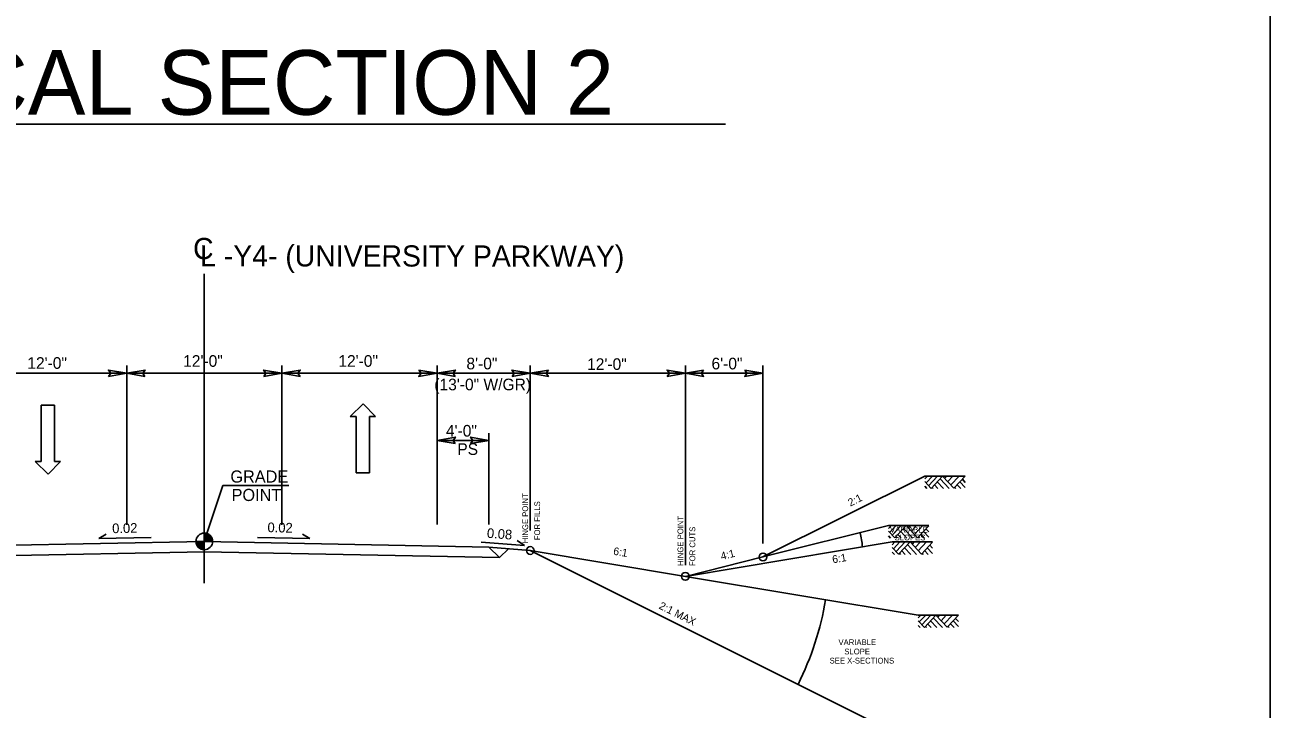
# Model space of a CAD drawing. Extents: x 1904401 to 1905163, y 193929 to 194736.
# Drawn here: x 1904562 to 1904658.3, y 194245.4 to 194298.3 of the extents above; entities that cross this region are included whole.
import ezdxf

# ---------------------------------------------------------------- set-up
doc = ezdxf.new("R2010")
doc.units = 0
for name, color, linetype in [('Old_Level_2', 7, 'Continuous'), ('Prop Lane Arrow CELL', 7, 'Continuous'), ('Typical Arrow Superelevation CELL', 7, 'Continuous'), ('Typical Grade Point Symbol CELL', 7, 'Continuous'), ('Typical Hinge Slope Arterial CELL', 7, 'Continuous'), ('Typical Terminator CELL', 7, 'Continuous'), ('Typical Text Centerline CELL', 7, 'Continuous'), ('Typical Text Grade Point CELL', 7, 'Continuous')]:
    doc.layers.add(name, color=color, linetype=linetype)

msp = doc.modelspace()

# ---------------------------------------------------------------- linework, layer by layer
at = {"layer": 'Old_Level_2'}
msp.add_lwpolyline([(1904502.509, 194232.165), (1904658.329, 194232.165), (1904658.329, 194351.235), (1904502.509, 194351.235)], close=True, dxfattribs=at)
at = {"layer": 'Prop Lane Arrow CELL'}
for p, q in [((1904534.927, 194290.618), (1904616.206, 194290.618)), ((1904569.917, 194271.945), (1904569.917, 194259.611)), ((1904581.917, 194271.945), (1904581.917, 194259.611)), ((1904593.917, 194271.945), (1904593.917, 194259.633)), ((1904601.117, 194271.945), (1904601.117, 194259.174)), ((1904613.115, 194271.945), (1904613.115, 194256.508)), ((1904619.114, 194271.945), (1904619.114, 194258.167)), ((1904569.917, 194271.345), (1904557.917, 194271.345)), ((1904581.917, 194271.345), (1904569.917, 194271.345)), ((1904581.917, 194271.345), (1904593.917, 194271.345)), ((1904619.114, 194271.345), (1904593.917, 194271.345)), ((1904563.311, 194268.879), (1904564.338, 194268.879)), ((1904563.311, 194264.521), (1904563.311, 194268.879)), ((1904564.338, 194268.879), (1904564.338, 194264.521)), ((1904588.197, 194268.973), (1904587.201, 194267.993)), ((1904589.162, 194267.993), (1904588.197, 194268.973)), ((1904587.201, 194267.993), (1904587.668, 194267.993)), ((1904587.668, 194267.993), (1904587.668, 194263.635)), ((1904588.695, 194263.635), (1904588.695, 194267.993)), ((1904588.695, 194267.993), (1904589.162, 194267.993)), ((1904597.917, 194266.721), (1904597.917, 194259.633)), ((1904597.917, 194266.153), (1904593.917, 194266.153)), ((1904563.84, 194263.541), (1904562.844, 194264.521)), ((1904562.844, 194264.521), (1904563.311, 194264.521)), ((1904564.805, 194264.521), (1904563.84, 194263.541)), ((1904564.338, 194264.521), (1904564.805, 194264.521)), ((1904587.668, 194263.635), (1904588.695, 194263.635)), ((1904631.838, 194263.392), (1904631.634, 194263.173)), ((1904632.119, 194262.436), (1904631.634, 194262.958)), ((1904632.222, 194263.392), (1904631.725, 194262.859)), ((1904632.622, 194263.392), (1904631.926, 194262.645)), ((1904633.008, 194263.391), (1904632.119, 194262.436)), ((1904633.07, 194262.426), (1904632.59, 194262.941)), ((1904633.514, 194262.426), (1904632.81, 194263.18)), ((1904633.886, 194262.448), (1904633.008, 194263.391)), ((1904633.325, 194263.392), (1904633.166, 194263.221)), ((1904633.807, 194263.392), (1904633.408, 194262.961)), ((1904634.285, 194263.392), (1904633.646, 194262.704)), ((1904634.754, 194263.383), (1904633.886, 194262.448)), ((1904634.754, 194262.502), (1904634.344, 194262.941)), ((1904634.754, 194262.901), (1904634.531, 194263.141)), ((1904631.795, 194262.426), (1904631.634, 194262.598)), ((1904632.276, 194262.426), (1904632.194, 194262.515)), ((1904632.63, 194262.426), (1904632.37, 194262.706)), ((1904634.036, 194262.426), (1904633.95, 194262.517)), ((1904634.409, 194262.426), (1904634.136, 194262.718)), ((1904629.018, 194259.557), (1904628.814, 194259.338)), ((1904629.299, 194258.601), (1904628.814, 194259.123)), ((1904629.402, 194259.557), (1904628.905, 194259.024)), ((1904629.802, 194259.557), (1904629.106, 194258.81)), ((1904630.188, 194259.556), (1904629.299, 194258.601)), ((1904630.249, 194258.591), (1904629.769, 194259.106)), ((1904630.694, 194258.591), (1904629.99, 194259.345)), ((1904631.066, 194258.613), (1904630.188, 194259.556)), ((1904630.505, 194259.557), (1904630.345, 194259.386)), ((1904630.987, 194259.557), (1904630.588, 194259.126)), ((1904631.465, 194259.557), (1904630.826, 194258.869)), ((1904631.934, 194259.548), (1904631.066, 194258.613)), ((1904631.934, 194258.667), (1904631.524, 194259.106)), ((1904631.934, 194259.066), (1904631.711, 194259.306)), ((1904575.917, 194258.339), (1904553.917, 194257.899)), ((1904575.917, 194258.339), (1904597.917, 194257.899)), ((1904628.975, 194258.591), (1904628.814, 194258.763)), ((1904629.317, 194258.299), (1904629.113, 194258.079)), ((1904629.701, 194258.299), (1904629.204, 194257.766)), ((1904629.456, 194258.591), (1904629.373, 194258.68)), ((1904630.1, 194258.299), (1904629.404, 194257.552)), ((1904629.81, 194258.591), (1904629.55, 194258.871)), ((1904630.487, 194258.298), (1904629.598, 194257.343)), ((1904630.992, 194257.333), (1904630.289, 194258.087)), ((1904631.364, 194257.354), (1904630.487, 194258.298)), ((1904630.804, 194258.299), (1904630.644, 194258.128)), ((1904631.286, 194258.299), (1904630.886, 194257.868)), ((1904631.763, 194258.299), (1904631.124, 194257.611)), ((1904631.216, 194258.591), (1904631.13, 194258.682)), ((1904631.589, 194258.591), (1904631.316, 194258.883)), ((1904632.233, 194258.289), (1904631.364, 194257.354)), ((1904632.233, 194257.808), (1904632.01, 194258.048)), ((1904575.933, 194257.535), (1904553.097, 194257.078)), ((1904575.901, 194257.535), (1904598.738, 194257.078)), ((1904598.738, 194257.078), (1904597.917, 194257.899)), ((1904597.917, 194257.899), (1904601.117, 194257.632)), ((1904598.738, 194257.078), (1904599.432, 194257.773)), ((1904629.598, 194257.343), (1904629.113, 194257.865)), ((1904629.274, 194257.333), (1904629.113, 194257.505)), ((1904629.755, 194257.333), (1904629.672, 194257.422)), ((1904630.109, 194257.333), (1904629.848, 194257.613)), ((1904630.548, 194257.333), (1904630.068, 194257.848)), ((1904631.514, 194257.333), (1904631.429, 194257.424)), ((1904631.887, 194257.333), (1904631.615, 194257.625)), ((1904632.233, 194257.409), (1904631.822, 194257.848)), ((1904631.316, 194252.633), (1904631.112, 194252.413)), ((1904631.597, 194251.677), (1904631.113, 194252.199)), ((1904631.701, 194252.633), (1904631.204, 194252.1)), ((1904632.1, 194252.633), (1904631.404, 194251.885)), ((1904632.487, 194252.632), (1904631.597, 194251.677)), ((1904632.548, 194251.667), (1904632.068, 194252.182)), ((1904632.992, 194251.667), (1904632.288, 194252.421)), ((1904633.364, 194251.688), (1904632.487, 194252.632)), ((1904632.803, 194252.633), (1904632.644, 194252.461)), ((1904633.286, 194252.633), (1904632.886, 194252.202)), ((1904633.763, 194252.633), (1904633.124, 194251.945)), ((1904634.233, 194252.623), (1904633.364, 194251.688)), ((1904634.233, 194251.742), (1904633.822, 194252.182)), ((1904634.233, 194252.142), (1904634.009, 194252.382)), ((1904631.273, 194251.667), (1904631.112, 194251.839)), ((1904631.755, 194251.667), (1904631.672, 194251.756)), ((1904632.109, 194251.667), (1904631.848, 194251.947)), ((1904633.514, 194251.667), (1904633.428, 194251.758)), ((1904633.887, 194251.667), (1904633.615, 194251.959))]:
    msp.add_line(p, q, dxfattribs=at)
for points in [[(1904634.754, 194263.392), (1904631.634, 194263.392)], [(1904631.934, 194259.557), (1904628.814, 194259.557)], [(1904632.233, 194258.299), (1904629.113, 194258.299)], [(1904634.233, 194252.633), (1904631.113, 194252.633)]]:
    msp.add_lwpolyline(points, dxfattribs=at)
at = {"layer": 'Typical Arrow Superelevation CELL'}
for p, q in [((1904567.754, 194258.565), (1904568.318, 194258.906)), ((1904584.08, 194258.565), (1904583.517, 194258.906)), ((1904567.754, 194258.565), (1904571.804, 194258.646)), ((1904584.08, 194258.565), (1904580.031, 194258.646)), ((1904600.664, 194258.031), (1904597.317, 194258.276)), ((1904600.664, 194258.031), (1904600.119, 194258.401))]:
    msp.add_line(p, q, dxfattribs=at)
at = {"layer": 'Typical Grade Point Symbol CELL'}
for p, q in [((1904575.917, 194258.339), (1904575.93, 194258.983)), ((1904575.273, 194258.351), (1904575.917, 194258.339)), ((1904575.903, 194257.694), (1904575.917, 194258.339)), ((1904575.917, 194258.339), (1904575.903, 194257.694)), ((1904576.562, 194258.326), (1904575.917, 194258.339))]:
    msp.add_line(p, q, dxfattribs=at)
for points in [[(1904575.936, 194258.983), (1904575.936, 194258.983), (1904575.923, 194258.339)], [(1904575.949, 194258.983), (1904575.936, 194258.338)], [(1904575.961, 194258.981), (1904575.949, 194258.338)], [(1904575.974, 194258.981), (1904575.962, 194258.338)], [(1904575.987, 194258.979), (1904575.975, 194258.338)], [(1904576, 194258.978), (1904575.988, 194258.337)], [(1904576.013, 194258.976), (1904576, 194258.337)], [(1904576.026, 194258.974), (1904576.013, 194258.337)], [(1904576.039, 194258.973), (1904576.026, 194258.337)], [(1904576.051, 194258.97), (1904576.039, 194258.336)], [(1904576.064, 194258.966), (1904576.052, 194258.336)], [(1904576.077, 194258.963), (1904576.065, 194258.336)], [(1904576.09, 194258.96), (1904576.078, 194258.336)], [(1904576.103, 194258.956), (1904576.091, 194258.335)], [(1904576.116, 194258.952), (1904576.104, 194258.335)], [(1904576.128, 194258.948), (1904576.116, 194258.335)], [(1904576.141, 194258.943), (1904576.129, 194258.335)], [(1904576.154, 194258.939), (1904576.142, 194258.334)], [(1904576.167, 194258.933), (1904576.155, 194258.334)], [(1904576.18, 194258.927), (1904576.168, 194258.334)], [(1904576.192, 194258.921), (1904576.181, 194258.334)], [(1904576.205, 194258.915), (1904576.194, 194258.333)], [(1904576.218, 194258.909), (1904576.207, 194258.333)], [(1904576.231, 194258.902), (1904576.22, 194258.333)], [(1904576.243, 194258.894), (1904576.232, 194258.333)], [(1904575.276, 194258.351), (1904575.274, 194258.281)], [(1904575.289, 194258.351), (1904575.286, 194258.205)], [(1904575.301, 194258.351), (1904575.298, 194258.159)], [(1904575.314, 194258.351), (1904575.31, 194258.12)], [(1904575.327, 194258.35), (1904575.322, 194258.09)], [(1904575.34, 194258.35), (1904575.335, 194258.062)], [(1904575.353, 194258.35), (1904575.347, 194258.038)], [(1904575.366, 194258.35), (1904575.359, 194258.014)], [(1904575.379, 194258.349), (1904575.372, 194257.994)], [(1904575.392, 194258.349), (1904575.384, 194257.975)], [(1904575.405, 194258.349), (1904575.397, 194257.958)], [(1904575.417, 194258.349), (1904575.41, 194257.942)], [(1904575.43, 194258.348), (1904575.422, 194257.926)], [(1904575.443, 194258.348), (1904575.435, 194257.911)], [(1904575.456, 194258.348), (1904575.447, 194257.897)], [(1904575.469, 194258.348), (1904575.46, 194257.884)], [(1904575.482, 194258.347), (1904575.473, 194257.872)], [(1904575.495, 194258.347), (1904575.485, 194257.86)], [(1904575.508, 194258.347), (1904575.498, 194257.848)], [(1904575.521, 194258.347), (1904575.511, 194257.838)], [(1904575.534, 194258.346), (1904575.523, 194257.828)], [(1904575.546, 194258.346), (1904575.536, 194257.819)], [(1904575.559, 194258.346), (1904575.549, 194257.81)], [(1904575.572, 194258.346), (1904575.562, 194257.801)], [(1904575.585, 194258.345), (1904575.574, 194257.793)], [(1904575.598, 194258.345), (1904575.587, 194257.785)], [(1904575.611, 194258.345), (1904575.6, 194257.778)], [(1904575.624, 194258.345), (1904575.613, 194257.77)], [(1904575.637, 194258.344), (1904575.625, 194257.764)], [(1904575.65, 194258.344), (1904575.638, 194257.758)], [(1904575.662, 194258.344), (1904575.651, 194257.752)], [(1904575.675, 194258.344), (1904575.664, 194257.746)], [(1904575.688, 194258.343), (1904575.676, 194257.74)], [(1904575.701, 194258.343), (1904575.689, 194257.736)], [(1904575.714, 194258.343), (1904575.702, 194257.731)], [(1904575.727, 194258.343), (1904575.715, 194257.727)], [(1904575.74, 194258.342), (1904575.728, 194257.724)], [(1904575.753, 194258.342), (1904575.74, 194257.719)], [(1904575.766, 194258.342), (1904575.753, 194257.716)], [(1904575.778, 194258.342), (1904575.766, 194257.713)], [(1904575.791, 194258.341), (1904575.779, 194257.71)], [(1904575.804, 194258.341), (1904575.792, 194257.707)], [(1904575.817, 194258.341), (1904575.805, 194257.705)], [(1904575.83, 194258.341), (1904575.817, 194257.702)], [(1904575.843, 194258.34), (1904575.83, 194257.7)], [(1904575.856, 194258.34), (1904575.843, 194257.698)], [(1904575.869, 194258.34), (1904575.856, 194257.697)], [(1904575.882, 194258.34), (1904575.869, 194257.696)], [(1904575.894, 194258.339), (1904575.882, 194257.695)], [(1904575.907, 194258.339), (1904575.895, 194257.695), (1904575.895, 194257.695)], [(1904576.256, 194258.887), (1904576.245, 194258.332)], [(1904576.269, 194258.879), (1904576.258, 194258.332)], [(1904576.282, 194258.87), (1904576.271, 194258.332)], [(1904576.294, 194258.862), (1904576.284, 194258.332)], [(1904576.307, 194258.851), (1904576.297, 194258.331)], [(1904576.32, 194258.842), (1904576.31, 194258.331)], [(1904576.333, 194258.832), (1904576.323, 194258.331)], [(1904576.345, 194258.821), (1904576.336, 194258.331)], [(1904576.358, 194258.809), (1904576.348, 194258.33)], [(1904576.37, 194258.797), (1904576.361, 194258.33)], [(1904576.383, 194258.784), (1904576.374, 194258.33)], [(1904576.396, 194258.771), (1904576.387, 194258.33)], [(1904576.408, 194258.756), (1904576.4, 194258.329)], [(1904576.421, 194258.74), (1904576.413, 194258.329)], [(1904576.434, 194258.724), (1904576.426, 194258.329)], [(1904576.446, 194258.707), (1904576.439, 194258.329)], [(1904576.459, 194258.688), (1904576.452, 194258.328)], [(1904576.471, 194258.668), (1904576.465, 194258.328)], [(1904576.484, 194258.646), (1904576.477, 194258.328)], [(1904576.496, 194258.623), (1904576.49, 194258.328)], [(1904576.508, 194258.595), (1904576.503, 194258.327)], [(1904576.521, 194258.565), (1904576.516, 194258.327)], [(1904576.533, 194258.529), (1904576.529, 194258.327)], [(1904576.545, 194258.484), (1904576.542, 194258.327)], [(1904576.557, 194258.418), (1904576.555, 194258.326)]]:
    msp.add_lwpolyline(points, dxfattribs=at)
msp.add_circle((1904575.917, 194258.339), 0.645, dxfattribs=at)
for start, end in [(358.87068, 88.87068), (178.87068, 268.87068)]:
    msp.add_arc((1904575.917, 194258.339), 0.645, start, end, dxfattribs=at)
at = {"layer": 'Typical Hinge Slope Arterial CELL'}
for p, q in [((1904631.634, 194263.392), (1904619.114, 194257.132)), ((1904628.814, 194259.557), (1904619.114, 194257.132)), ((1904629.113, 194258.299), (1904613.115, 194255.632)), ((1904613.115, 194255.632), (1904601.117, 194257.632)), ((1904631.113, 194242.635), (1904601.117, 194257.632)), ((1904619.114, 194257.132), (1904613.115, 194255.632)), ((1904631.113, 194252.633), (1904613.115, 194255.632))]:
    msp.add_line(p, q, dxfattribs=at)
for centre in [(1904601.117, 194257.632), (1904619.114, 194257.132), (1904613.115, 194255.632)]:
    msp.add_circle(centre, 0.297, dxfattribs=at)
for centre, radius, start, end in [((1904619.114, 194257.132), 7.737, 5.81028, 14.03631), ((1904601.117, 194257.632), 23.155, 333.43495, 350.53755)]:
    msp.add_arc(centre, radius, start, end, dxfattribs=at)
at = {"layer": 'Typical Terminator CELL'}
for points in [[(1904568.511, 194271.102), (1904569.917, 194271.345), (1904568.503, 194271.595), (1904568.683, 194271.345)], [(1904571.323, 194271.102), (1904569.917, 194271.345), (1904571.331, 194271.595), (1904571.152, 194271.345)], [(1904580.511, 194271.102), (1904581.917, 194271.345), (1904580.503, 194271.595), (1904580.683, 194271.345)], [(1904583.323, 194271.102), (1904581.917, 194271.345), (1904583.331, 194271.595), (1904583.152, 194271.345)], [(1904592.511, 194271.587), (1904593.917, 194271.345), (1904592.503, 194271.095), (1904592.683, 194271.345)], [(1904595.323, 194271.102), (1904593.917, 194271.345), (1904595.331, 194271.595), (1904595.152, 194271.345)], [(1904599.711, 194271.102), (1904601.117, 194271.345), (1904599.703, 194271.595), (1904599.883, 194271.345)], [(1904602.523, 194271.587), (1904601.117, 194271.345), (1904602.531, 194271.095), (1904602.352, 194271.345)], [(1904611.709, 194271.102), (1904613.115, 194271.345), (1904611.702, 194271.595), (1904611.881, 194271.345)], [(1904614.521, 194271.587), (1904613.115, 194271.345), (1904614.529, 194271.095), (1904614.35, 194271.345)], [(1904617.708, 194271.587), (1904619.114, 194271.345), (1904617.701, 194271.095), (1904617.88, 194271.345)], [(1904595.323, 194265.911), (1904593.917, 194266.153), (1904595.331, 194266.403), (1904595.152, 194266.153)], [(1904596.511, 194265.911), (1904597.917, 194266.153), (1904596.503, 194266.403), (1904596.683, 194266.153)]]:
    msp.add_lwpolyline(points, close=True, dxfattribs=at)
at = {"layer": 'Typical Text Centerline CELL'}
msp.add_line((1904575.917, 194279.031), (1904575.917, 194255.107), dxfattribs=at)
at = {"layer": 'Typical Text Grade Point CELL'}
for p in [(1904575.917, 194258.339), (1904582.453, 194262.659)]:
    msp.add_line(p, (1904577.357, 194262.659), dxfattribs=at)

# ---------------------------------------------------------------- texts
at = {"layer": 'Prop Lane Arrow CELL'}
for s, height, p in [('TYPICAL SECTION 2', 5, (1904542.577, 194291.344)), ('12\'-0"', 0.9, (1904562.23, 194271.688)), ('12\'-0"', 0.9, (1904574.28, 194271.845)), ('12\'-0"', 0.9, (1904586.28, 194271.845)), ('8\'-0"', 0.9, (1904596.183, 194271.646)), ('12\'-0"', 0.9, (1904605.516, 194271.602)), ('6\'-0"', 0.9, (1904615.136, 194271.646)), ('(13\'-0" W/GR)', 0.9, (1904593.703, 194270.027)), ('4\'-0"', 0.9, (1904594.6, 194266.445)), ('PS', 0.9, (1904595.481, 194265.026))]:
    msp.add_text(s, height=height, dxfattribs=at).set_placement(p)
for s, rotation, p in [('0.02', 1.1462, (1904568.798, 194258.969)), ('0.02', 358.8538, (1904580.795, 194259.051)), ('0.08', 355.80177, (1904597.748, 194258.616))]:
    msp.add_text(s, height=0.7499, rotation=rotation, dxfattribs=at).set_placement(p)
at = {"layer": 'Typical Hinge Slope Arterial CELL'}
for s, height, rotation, p in [('HINGE POINT ', 0.44524, 90, (1904600.956, 194258.188)), ('2:1', 0.5937, 26.56505, (1904625.872, 194261.022)), ('FOR FILLS', 0.4452, 90, (1904601.881, 194258.43)), ('HINGE POINT ', 0.44524, 90, (1904612.954, 194256.442)), ('FOR CUTS', 0.4452, 90, (1904613.879, 194256.43)), ('6:1', 0.5937, 350.53768, (1904607.51, 194257.311)), ('4:1', 0.5936, 14.03624, (1904615.919, 194256.888)), ('6:1', 0.5937, 9.46348, (1904624.524, 194256.639)), ('2:1 MAX', 0.5937, 333.43495, (1904611.016, 194253.164))]:
    msp.add_text(s, height=height, rotation=rotation, dxfattribs=at).set_placement(p)
for s, height, p in [('VARIABLE ', 0.4452, (1904628.941, 194259.024)), ('SLOPES', 0.4452, (1904629.294, 194258.414)), ('VARIABLE ', 0.4452, (1904624.953, 194250.313)), ('SEE X-SECTIONS', 0.44524, (1904624.267, 194248.888)), ('SLOPE', 0.4452, (1904625.404, 194249.593))]:
    msp.add_text(s, height=height, dxfattribs=at).set_placement(p)
at = {"layer": 'Typical Text Centerline CELL'}
msp.add_text('C', height=1.64, dxfattribs=at).set_placement((1904575.049, 194280.174))
msp.add_text('L -Y4- (UNIVERSITY PARKWAY) ', height=1.64109, rotation=359.9469, dxfattribs=at).set_placement((1904575.594, 194279.614))
at = {"layer": 'Typical Text Grade Point CELL'}
for s, p in [('GRADE', (1904577.935, 194262.884)), ('POINT', (1904578.026, 194261.46))]:
    msp.add_text(s, height=0.9397, rotation=360, dxfattribs=at).set_placement(p)

doc.saveas('drawing.dxf')
